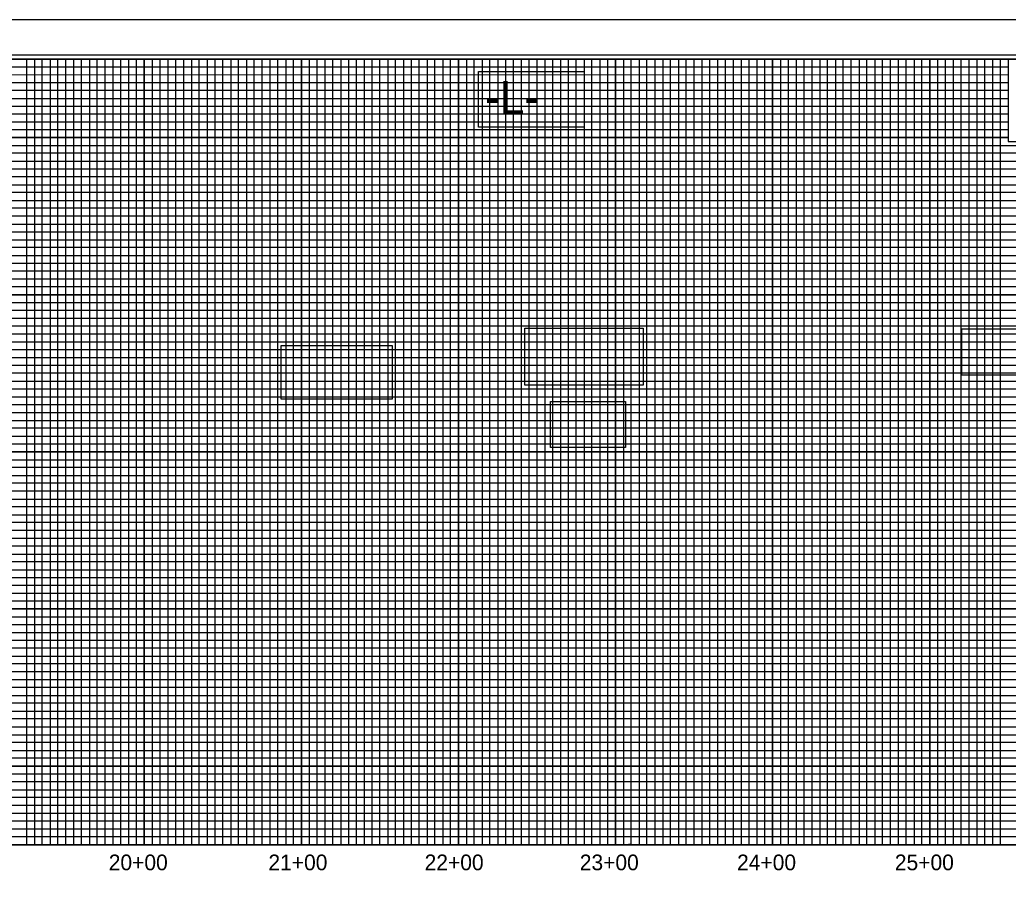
# Model space of a CAD drawing. Extents: x 1810963 to 1812948, y 722070 to 723250.
# Drawn here: x 1811601 to 1812230, y 722624 to 723170 of the extents above; entities that cross this region are included whole.
import ezdxf

# ---------------------------------------------------------------- set-up
doc = ezdxf.new("R2010")
doc.units = 0
for name, color, linetype in [('Exist Vertical Profile Horizontal Axis Label Major', 7, 'Continuous'), ('Prop Grid Mask', 7, 'Continuous'), ('Prop Horizontal Alignment Station Label', 7, 'Continuous'), ('Scratch_Level_3', 7, 'Continuous'), ('Sheet Cutting Line CELL', 7, 'Continuous'), ('Sheet DOT Grid CELL', 7, 'Continuous'), ('Sheet Layout Profile Border Port 1', 7, 'Continuous'), ('Sheet Plot Border Inside CELL', 7, 'Continuous'), ('Sheet Plot Border Outside CELL', 7, 'Continuous'), ('Sheet Profile CELL', 7, 'Continuous'), ('Sheet Profile Grid Major CELL', 7, 'Continuous'), ('Sheet Profile Grid Middle CELL', 7, 'Continuous'), ('Sheet Profile Grid Minor CELL', 7, 'Continuous')]:
    doc.layers.add(name, color=color, linetype=linetype)

msp = doc.modelspace()

# ---------------------------------------------------------------- linework, layer by layer
at = {"layer": 'Prop Grid Mask'}
for points in [[(1811893.13, 723136.89), (1811960.48, 723136.89), (1811960.48, 723101.51), (1811893.13, 723101.51)], [(1811922.71, 722973.62), (1811998.01, 722973.62), (1811998.01, 722937.29), (1811922.71, 722937.29)], [(1812200.84, 722973.14), (1812279.39, 722973.14), (1812279.39, 722943.7), (1812200.84, 722943.7)], [(1811767.58, 722962.54), (1811838.14, 722962.54), (1811838.14, 722928.46), (1811767.58, 722928.46)], [(1811939, 722927), (1811986.88, 722927), (1811986.88, 722897.67), (1811939, 722897.67)]]:
    msp.add_lwpolyline(points, close=True, dxfattribs=at)
at = {"layer": 'Scratch_Level_3'}
msp.add_lwpolyline([(1811180.46, 723144.88), (1812230.46, 723144.88), (1812230.46, 723092.45), (1812430.5, 723092.45), (1812430.41, 722983.83), (1812580.46, 722983.83), (1812580.46, 722644.88), (1811180.46, 722644.88)], close=True, dxfattribs=at)
at = {"layer": 'Sheet Cutting Line CELL'}
msp.add_line((1812647.46, 723169.88), (1810963.46, 723169.88), dxfattribs=at)
at = {"layer": 'Sheet DOT Grid CELL'}
for p, q in [((1811630.46, 722644.88), (1811630.46, 723144.88)), ((1811680.46, 722644.88), (1811680.46, 723144.88)), ((1811730.46, 722644.88), (1811730.46, 723144.88)), ((1811780.46, 722644.88), (1811780.46, 723144.88)), ((1811830.46, 722644.88), (1811830.46, 723144.88)), ((1811880.46, 722644.88), (1811880.46, 723144.88)), ((1811930.46, 722644.88), (1811930.46, 723144.88)), ((1811980.46, 722644.88), (1811980.46, 723144.88)), ((1812030.46, 722644.88), (1812030.46, 723144.88)), ((1812080.46, 722644.88), (1812080.46, 723144.88)), ((1812130.46, 722644.88), (1812130.46, 723144.88)), ((1812180.46, 722644.88), (1812180.46, 723144.88)), ((1812230.42, 723094.88), (1811130.46, 723094.88)), ((1812430.41, 723044.88), (1811130.46, 723044.88)), ((1812430.46, 722994.88), (1811130.46, 722994.88)), ((1812630.46, 722944.88), (1811130.46, 722944.88)), ((1812630.46, 722894.88), (1811130.46, 722894.88)), ((1812630.46, 722844.88), (1811130.46, 722844.88)), ((1812630.46, 722794.88), (1811130.46, 722794.88)), ((1812630.46, 722744.88), (1811130.46, 722744.88)), ((1812630.46, 722694.88), (1811130.46, 722694.88))]:
    msp.add_line(p, q, dxfattribs=at)
at = {"layer": 'Sheet Layout Profile Border Port 1'}
msp.add_lwpolyline([(1811180.46, 722983.83), (1811180.46, 722644.88), (1812580.46, 722644.88), (1812580.46, 722983.83)], dxfattribs=at)
at = {"layer": 'Sheet Plot Border Inside CELL'}
msp.add_lwpolyline([(1810976.46, 722092.33), (1812642.96, 722092.33), (1812642.96, 723147.43), (1810976.46, 723147.43)], close=True, dxfattribs=at)
at = {"layer": 'Sheet Plot Border Outside CELL'}
msp.add_lwpolyline([(1810963.46, 722069.88), (1812647.46, 722069.88), (1812647.46, 723169.88), (1810963.46, 723169.88)], close=True, dxfattribs=at)
at = {"layer": 'Sheet Profile CELL'}
msp.add_line((1811130.46, 722644.88), (1812630.46, 722644.88), dxfattribs=at)
msp.add_lwpolyline([(1812630.46, 723144.88), (1811130.46, 723144.88), (1811130.46, 722094.88), (1812630.46, 722094.88)], close=True, dxfattribs=at)
at = {"layer": 'Sheet Profile Grid Major CELL'}
for points in [[(1811580.46, 722644.88), (1811630.46, 722644.88), (1811630.46, 723144.88), (1811680.46, 723144.88), (1811680.46, 722644.88), (1811730.46, 722644.88), (1811730.46, 723144.88), (1811780.46, 723144.88), (1811780.46, 722644.88), (1811830.46, 722644.88), (1811830.46, 723144.88), (1811880.46, 723144.88), (1811880.46, 722644.88), (1811930.46, 722644.88), (1811930.46, 723144.88), (1811980.46, 723144.88), (1811980.46, 722644.88), (1812030.46, 722644.88), (1812030.46, 723144.88), (1812080.46, 723144.88), (1812080.46, 722644.88), (1812130.46, 722644.88), (1812130.46, 723144.88), (1812180.46, 723144.88), (1812180.46, 722644.88), (1812230.46, 722644.88)], [(1811130.46, 723094.88), (1812230.42, 723094.88)], [(1812430.46, 723044.88), (1811130.46, 723044.88), (1811130.46, 722994.88), (1812430.46, 722994.88)], [(1812630.46, 722944.88), (1811130.46, 722944.88), (1811130.46, 722894.88), (1812630.46, 722894.88)], [(1812630.46, 722844.88), (1811130.46, 722844.88), (1811130.46, 722794.88), (1812630.46, 722794.88)], [(1812630.46, 722744.88), (1811130.46, 722744.88), (1811130.46, 722744.88), (1811130.46, 722694.88), (1812630.46, 722694.88)]]:
    msp.add_lwpolyline(points, dxfattribs=at)
at = {"layer": 'Sheet Profile Grid Middle CELL'}
for p, q in [((1811555.46, 723144.88), (1811605.46, 723144.88)), ((1811605.46, 723144.88), (1811605.46, 722644.88)), ((1811655.46, 722644.88), (1811655.46, 723144.88)), ((1811655.46, 723144.88), (1811705.46, 723144.88)), ((1811705.46, 723144.88), (1811705.46, 722644.88)), ((1811755.46, 722644.88), (1811755.46, 723144.88)), ((1811755.46, 723144.88), (1811805.46, 723144.88)), ((1811805.46, 723144.88), (1811805.46, 722644.88)), ((1811855.46, 722644.88), (1811855.46, 723144.88)), ((1811855.46, 723144.88), (1811905.46, 723144.88)), ((1811905.46, 723144.88), (1811905.46, 722644.88)), ((1811955.46, 722644.88), (1811955.46, 723144.88)), ((1811955.46, 723144.88), (1812005.46, 723144.88)), ((1812005.46, 723144.88), (1812005.46, 722644.88)), ((1812055.46, 722644.88), (1812055.46, 723144.88)), ((1812055.46, 723144.88), (1812105.46, 723144.88)), ((1812105.46, 723144.88), (1812105.46, 722644.88)), ((1812155.46, 722644.88), (1812155.46, 723144.88)), ((1812155.46, 723144.88), (1812205.46, 723144.88)), ((1812205.46, 723144.88), (1812205.46, 722644.88)), ((1811130.46, 723119.88), (1812230.42, 723119.88)), ((1811605.46, 722644.88), (1811655.46, 722644.88)), ((1811705.46, 722644.88), (1811755.46, 722644.88)), ((1811755.46, 722644.88), (1811755.46, 722644.88)), ((1811805.46, 722644.88), (1811855.46, 722644.88)), ((1811905.46, 722644.88), (1811955.46, 722644.88)), ((1812005.46, 722644.88), (1812055.46, 722644.88)), ((1812105.46, 722644.88), (1812155.46, 722644.88)), ((1812205.46, 722644.88), (1812255.46, 722644.88))]:
    msp.add_line(p, q, dxfattribs=at)
for points in [[(1812430.46, 723069.88), (1811130.46, 723069.88), (1811130.46, 723019.88), (1812430.46, 723019.88)], [(1812630.46, 722969.88), (1811130.46, 722969.88), (1811130.46, 722919.88), (1812455.46, 722919.88)], [(1812630.46, 722869.88), (1811130.46, 722869.88), (1811130.46, 722819.88), (1812630.46, 722819.88)], [(1812630.46, 722769.88), (1811130.46, 722769.88), (1811130.46, 722719.88), (1812630.46, 722719.88)], [(1812630.46, 722669.88), (1811130.46, 722669.88)]]:
    msp.add_lwpolyline(points, dxfattribs=at)
at = {"layer": 'Sheet Profile Grid Minor CELL'}
for p, q in [((1812015.46, 722644.88), (1812015.46, 723144.88)), ((1812015.46, 723144.88), (1812020.46, 723144.88)), ((1812020.46, 723144.88), (1812020.46, 722644.88)), ((1812025.46, 722644.88), (1812025.46, 723144.88)), ((1812025.46, 723144.88), (1812035.46, 723144.88)), ((1812035.46, 723144.88), (1812035.46, 722644.88)), ((1812040.46, 722644.88), (1812040.46, 723144.88)), ((1812040.46, 723144.88), (1812045.46, 723144.88)), ((1812045.46, 723144.88), (1812045.46, 722644.88)), ((1812050.46, 722644.88), (1812050.46, 723144.88)), ((1812050.46, 723144.88), (1812060.46, 723144.88)), ((1812060.46, 723144.88), (1812060.46, 722644.88)), ((1812065.46, 722644.88), (1812065.46, 723144.88)), ((1812065.46, 723144.88), (1812070.46, 723144.88)), ((1812070.46, 723144.88), (1812070.46, 722644.88)), ((1812075.46, 722644.88), (1812075.46, 723144.88)), ((1812075.46, 723144.88), (1812085.46, 723144.88)), ((1812085.46, 723144.88), (1812085.46, 722644.88)), ((1812090.46, 722644.88), (1812090.46, 723144.88)), ((1812090.46, 723144.88), (1812095.46, 723144.88)), ((1812095.46, 723144.88), (1812095.46, 722644.88)), ((1812100.46, 722644.88), (1812100.46, 723144.88)), ((1812100.46, 723144.88), (1812110.46, 723144.88)), ((1812110.46, 723144.88), (1812110.46, 722644.88)), ((1812115.46, 722644.88), (1812115.46, 723144.88)), ((1812115.46, 723144.88), (1812120.46, 723144.88)), ((1812120.46, 723144.88), (1812120.46, 722644.88)), ((1812125.46, 722644.88), (1812125.46, 723144.88)), ((1812125.46, 723144.88), (1812135.46, 723144.88)), ((1812135.46, 723144.88), (1812135.46, 722644.88)), ((1812140.46, 722644.88), (1812140.46, 723144.88)), ((1812140.46, 723144.88), (1812145.46, 723144.88)), ((1812145.46, 723144.88), (1812145.46, 722644.88)), ((1812150.46, 722644.88), (1812150.46, 723144.88)), ((1812150.46, 723144.88), (1812160.46, 723144.88)), ((1812160.46, 723144.88), (1812160.46, 722644.88)), ((1812165.46, 722644.88), (1812165.46, 723144.88)), ((1812165.46, 723144.88), (1812170.46, 723144.88)), ((1812170.46, 723144.88), (1812170.46, 722644.88)), ((1812175.46, 722644.88), (1812175.46, 723144.88)), ((1812175.46, 723144.88), (1812185.46, 723144.88)), ((1812185.46, 723144.88), (1812185.46, 722644.88)), ((1812190.46, 722644.88), (1812190.46, 723144.88)), ((1812190.46, 723144.88), (1812195.46, 723144.88)), ((1812195.46, 723144.88), (1812195.46, 722644.88)), ((1812200.46, 722644.88), (1812200.46, 723144.88)), ((1812200.46, 723144.88), (1812210.46, 723144.88)), ((1812210.46, 723144.88), (1812210.46, 722644.88)), ((1812215.46, 722644.88), (1812215.46, 723144.88)), ((1812215.46, 723144.88), (1812220.46, 723144.88)), ((1812220.46, 723144.88), (1812220.46, 722644.88)), ((1812225.46, 722644.88), (1812225.46, 723144.88)), ((1812225.46, 723144.88), (1812235.46, 723144.88)), ((1811180.46, 723139.88), (1812230.42, 723139.88)), ((1812230.42, 723134.82), (1811180.46, 723134.53)), ((1811180.46, 723129.88), (1812230.42, 723129.88)), ((1812230.42, 723099.88), (1811180.46, 723099.88)), ((1811180.46, 723089.88), (1812430.46, 723089.88)), ((1812430.41, 723009.88), (1811180.46, 723009.88)), ((1812430.46, 723004.88), (1811180.46, 723004.88)), ((1812430.46, 722999.88), (1811180.46, 722999.88)), ((1811180.46, 722989.88), (1812430.46, 722989.88)), ((1812430.46, 722984.88), (1811180.46, 722984.88)), ((1811180.46, 722979.88), (1812580.46, 722979.88)), ((1812580.46, 722959.88), (1811180.46, 722959.88)), ((1811180.46, 722954.88), (1812580.46, 722954.88)), ((1812580.46, 722934.88), (1811180.46, 722934.88)), ((1811180.46, 722929.88), (1812580.46, 722929.88)), ((1812580.46, 722909.88), (1811180.46, 722909.88)), ((1811180.46, 722904.88), (1812580.46, 722904.88)), ((1812580.46, 722899.88), (1811180.46, 722899.88)), ((1811180.46, 722889.88), (1812580.46, 722889.88)), ((1812580.46, 722884.88), (1811180.46, 722884.88)), ((1811180.46, 722879.88), (1812580.46, 722879.88)), ((1812580.46, 722874.88), (1811180.46, 722874.88)), ((1811180.46, 722864.88), (1812580.46, 722864.88)), ((1812580.46, 722859.88), (1811180.46, 722859.88)), ((1811180.46, 722854.88), (1812580.46, 722854.88)), ((1812580.46, 722849.88), (1811180.46, 722849.88)), ((1811180.46, 722839.88), (1812580.46, 722839.88)), ((1812580.46, 722834.88), (1811180.46, 722834.88)), ((1811180.46, 722829.88), (1812580.46, 722829.88)), ((1812580.46, 722824.88), (1811180.46, 722824.88)), ((1811180.46, 722814.88), (1812580.46, 722814.88)), ((1812580.46, 722809.88), (1811180.46, 722809.88)), ((1811180.46, 722804.88), (1812580.46, 722804.88)), ((1812580.46, 722799.88), (1811180.46, 722799.88)), ((1811180.46, 722789.88), (1812580.46, 722789.88)), ((1812580.46, 722784.88), (1811180.46, 722784.88)), ((1811180.46, 722779.88), (1812580.46, 722779.88)), ((1812580.46, 722774.88), (1811180.46, 722774.88)), ((1811180.46, 722764.88), (1812580.46, 722764.88)), ((1812580.46, 722759.88), (1811180.46, 722759.88)), ((1812580.46, 722754.88), (1811180.46, 722754.88)), ((1812580.46, 722749.88), (1811180.46, 722749.88)), ((1811180.46, 722739.88), (1812580.46, 722739.88)), ((1812580.46, 722734.88), (1811180.46, 722734.88)), ((1811180.46, 722729.88), (1812580.46, 722729.88)), ((1812580.46, 722724.88), (1811180.46, 722724.88)), ((1811180.46, 722714.88), (1812580.46, 722714.88)), ((1812580.46, 722709.88), (1811180.46, 722709.88)), ((1811180.46, 722704.88), (1812580.46, 722704.88)), ((1812580.46, 722699.88), (1811180.46, 722699.88)), ((1811180.46, 722689.88), (1812580.46, 722689.88)), ((1812580.46, 722684.88), (1811180.46, 722684.88)), ((1811180.46, 722679.88), (1812580.46, 722679.88)), ((1812580.46, 722674.88), (1811180.46, 722674.88)), ((1811180.46, 722664.88), (1812580.46, 722664.88)), ((1812580.46, 722659.88), (1811180.46, 722659.88)), ((1811180.46, 722654.88), (1812580.46, 722654.88)), ((1812020.46, 722644.88), (1812025.46, 722644.88)), ((1812035.46, 722644.88), (1812040.46, 722644.88)), ((1812045.46, 722644.88), (1812050.46, 722644.88)), ((1812060.46, 722644.88), (1812065.46, 722644.88)), ((1812070.46, 722644.88), (1812075.46, 722644.88)), ((1812085.46, 722644.88), (1812090.46, 722644.88)), ((1812095.46, 722644.88), (1812100.46, 722644.88)), ((1812110.46, 722644.88), (1812115.46, 722644.88)), ((1812120.46, 722644.88), (1812125.46, 722644.88)), ((1812135.46, 722644.88), (1812140.46, 722644.88)), ((1812145.46, 722644.88), (1812150.46, 722644.88)), ((1812160.46, 722644.88), (1812165.46, 722644.88)), ((1812170.46, 722644.88), (1812175.46, 722644.88)), ((1812185.46, 722644.88), (1812190.46, 722644.88)), ((1812195.46, 722644.88), (1812200.46, 722644.88)), ((1812210.46, 722644.88), (1812215.46, 722644.88)), ((1812220.46, 722644.88), (1812225.46, 722644.88))]:
    msp.add_line(p, q, dxfattribs=at)
for points in [[(1811600.46, 723144.88), (1811610.46, 723144.88), (1811610.46, 722644.88), (1811615.46, 722644.88), (1811615.46, 723144.88), (1811620.46, 723144.88), (1811620.46, 722644.88), (1811625.46, 722644.88), (1811625.46, 723144.88), (1811635.46, 723144.88), (1811635.46, 722644.88), (1811640.46, 722644.88), (1811640.46, 723144.88), (1811645.46, 723144.88), (1811645.46, 722644.88), (1811650.46, 722644.88), (1811650.46, 723144.88), (1811660.46, 723144.88), (1811660.46, 722644.88), (1811665.46, 722644.88), (1811665.46, 723144.88), (1811670.46, 723144.88), (1811670.46, 722644.88), (1811675.46, 722644.88), (1811675.46, 723144.88), (1811685.46, 723144.88), (1811685.46, 722644.88), (1811690.46, 722644.88), (1811690.46, 723144.88), (1811695.46, 723144.88), (1811695.46, 722644.88), (1811700.46, 722644.88), (1811700.46, 723144.88), (1811710.46, 723144.88)], [(1811710.46, 723144.88), (1811710.46, 722644.88), (1811715.46, 722644.88), (1811715.46, 723144.88), (1811720.46, 723144.88), (1811720.46, 722644.88), (1811725.46, 722644.88), (1811725.46, 723144.88), (1811735.46, 723144.88), (1811735.46, 722644.88), (1811740.46, 722644.88), (1811740.46, 723144.88), (1811745.46, 723144.88), (1811745.46, 722644.88), (1811750.46, 722644.88), (1811750.46, 723144.88), (1811760.46, 723144.88), (1811760.46, 722644.88), (1811765.46, 722644.88), (1811765.46, 723144.88), (1811770.46, 723144.88), (1811770.46, 722644.88), (1811775.46, 722644.88), (1811775.46, 723144.88), (1811785.46, 723144.88), (1811785.46, 722644.88), (1811790.46, 722644.88), (1811790.46, 723144.88), (1811795.46, 723144.88), (1811795.46, 722644.88), (1811800.46, 722644.88), (1811800.46, 723144.88), (1811810.46, 723144.88), (1811810.46, 722644.88), (1811815.46, 722644.88), (1811815.46, 723144.88), (1811820.46, 723144.88), (1811820.46, 722644.88), (1811825.46, 722644.88), (1811825.46, 723144.88), (1811835.46, 723144.88), (1811835.46, 722644.88), (1811835.46, 722644.88), (1811840.46, 722644.88), (1811840.46, 723144.88), (1811845.46, 723144.88), (1811845.46, 722644.88), (1811850.46, 722644.88), (1811850.46, 723144.88), (1811860.46, 723144.88), (1811860.46, 722644.88), (1811865.46, 722644.88), (1811865.46, 723144.88), (1811870.46, 723144.88), (1811870.46, 722644.88), (1811875.46, 722644.88), (1811875.46, 723144.88), (1811885.46, 723144.88), (1811885.46, 722644.88), (1811890.46, 722644.88), (1811890.46, 723144.88), (1811895.46, 723144.88), (1811895.46, 722644.88), (1811900.46, 722644.88), (1811900.46, 723144.88), (1811910.46, 723144.88), (1811910.46, 722644.88), (1811915.46, 722644.88), (1811915.46, 723144.88), (1811920.46, 723144.88), (1811920.46, 722644.88), (1811925.46, 722644.88), (1811925.46, 723144.88), (1811935.46, 723144.88), (1811935.46, 722644.88), (1811940.46, 722644.88), (1811940.46, 723144.88), (1811945.46, 723144.88), (1811945.46, 722644.88), (1811950.46, 722644.88), (1811950.46, 723144.88), (1811960.46, 723144.88), (1811960.46, 722644.88), (1811965.46, 722644.88), (1811965.46, 723144.88), (1811970.46, 723144.88), (1811970.46, 722644.88), (1811975.46, 722644.88), (1811975.46, 723144.88), (1811985.46, 723144.88), (1811985.46, 722644.88), (1811990.16, 722645.43), (1811990.46, 722644.88), (1811990.46, 723144.88), (1811995.46, 723144.88), (1811995.46, 722644.88), (1812000.46, 722644.88), (1812000.46, 723144.88), (1812010.46, 723144.88), (1812010.46, 722644.88), (1812015.46, 722644.88)], [(1812230.42, 723124.88), (1811180.46, 723124.88), (1811180.46, 723114.88), (1812230.42, 723114.88)], [(1812230.42, 723109.88), (1811180.46, 723109.88), (1811180.46, 723104.88), (1812230.42, 723104.88)], [(1812430.46, 723084.88), (1811180.46, 723084.88), (1811180.46, 723079.88), (1812430.46, 723079.88)], [(1812430.46, 723074.88), (1811180.46, 723074.88), (1811180.46, 723064.88), (1812430.46, 723064.88)], [(1812430.46, 723059.88), (1811180.46, 723059.88), (1811180.46, 723054.88), (1812430.46, 723054.88)], [(1812430.46, 723049.88), (1811180.46, 723049.88), (1811180.46, 723039.88), (1812430.46, 723039.88)], [(1812430.46, 723034.78), (1811180.56, 723034.78), (1811180.56, 723029.88), (1812430.46, 723029.88)], [(1812430.46, 723024.88), (1811180.46, 723024.88), (1811180.46, 723014.88), (1812430.46, 723014.88)], [(1812580.46, 722974.88), (1811180.46, 722974.88), (1811180.46, 722964.88), (1812580.46, 722964.88)], [(1812580.46, 722949.88), (1811180.46, 722949.88), (1811180.46, 722939.88), (1812580.46, 722939.88)], [(1812580.46, 722924.88), (1811180.46, 722924.88), (1811180.46, 722914.88), (1812580.46, 722914.88)], [(1812580.46, 722649.88), (1811180.46, 722649.88)]]:
    msp.add_lwpolyline(points, dxfattribs=at)

# ---------------------------------------------------------------- texts
at = {"layer": 'Exist Vertical Profile Horizontal Axis Label Major'}
for s, p in [('20+00', (1811657.81, 722628.6)), ('21+00', (1811759.46, 722628.6)), ('22+00', (1811858.9, 722628.6)), ('23+00', (1811957.68, 722628.6)), ('24+00', (1812057.81, 722628.6)), ('25+00', (1812158.26, 722628.6))]:
    msp.add_text(s, height=10, dxfattribs=at).set_placement(p)
at = {"layer": 'Prop Horizontal Alignment Station Label'}
msp.add_text('-L-', height=21, rotation=360, dxfattribs=at).set_placement((1811897.42, 723109.94))

doc.saveas('drawing.dxf')
